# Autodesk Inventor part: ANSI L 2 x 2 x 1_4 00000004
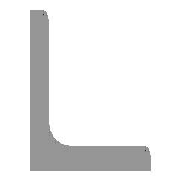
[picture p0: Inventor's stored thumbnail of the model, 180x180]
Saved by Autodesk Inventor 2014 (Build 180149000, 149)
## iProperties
IsCustomPart: 1
Created: 2007-02
Part Number: ANSI L 2 x 2 x 1_4 00000004
Material: Steel, Mild
Document SubType Name: Modeling
Standard: AISC
Designer: Autodesk, Inc.
Size Designation: L 2 x 2 x 1/4
Stock Number: L 2 x 2 x 1/4
Density: 7.86 g/cm^3
Description: Angle Steel
Standards Organization: ANSI
Language: en-US
Categories: <MemberInstance><Categories><Category DisplayName="Structural Shapes" InternalName="089c4875-fa83-4c05-b084-43b9cc11f5ed" Mnemonic="GRDR"><CategoryParameter Dis
Mass: 3582.18 g
Surface Area: 1508.05 cm^2
Volume: 455.748 cm^3
Appearance: Steel
_FrameMemberDoc: Frame Member File
_Version: 15.0.0
_CCFamilyMember: 11
_CCFamilyDisplayName: ANSI L (Equal angles) - Angle Steel
G_L: 31.000 in
G_W: 2.000 in
G_H: 2.000 in
+4F5F36E9-8B8F-4344-9F4B-B9E790CCB65B+CUTDETAIL1: Miter 45.00 deg
+83905929-4DA7-493A-BC2A-CF29B1304FE5+CUTDETAIL2: Miter 45.00 deg
Author: Autodesk, Inc.
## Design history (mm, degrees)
node "Start plane"
node "End plane"
sketch "Sketch"
  geometry: L1 (50.8, 0)-(0, 0); L2 (0, 0)-(0, 50.8); L3 (0, 50.8)-(3.302, 50.8); L4 (6.35, 47.752)-(6.35, 12.7); L5 (12.7, 6.35)-(47.752, 6.35); L6 (50.8, 3.302)-(50.8, 0); L7 (0, -11.041)-(0, 31.538); L8 (-11.041, 0)-(31.538, 0); L9 (0, 63.926)-(0, -23.536) reference; L10 (-23.536, 0)-(63.926, 0) reference; A1 r 6.35 centre (12.7, 12.7) between (6.35, 12.7) and (12.7, 6.35); A2 r 3.048 centre (3.302, 47.752) between (6.35, 47.752) and (3.302, 50.8); A3 r 3.048 centre (47.752, 3.302) between (50.8, 3.302) and (47.752, 6.35); 3 further points
  constraints: 16 end point, 6 point on circle, 6 point on line, 6 tangent, 4 parallel, 3 centre point, 2 collinear, 1 equal radius, 1 horizontal, 1 perpendicular
  dimensions: "d0" = 50.8 distance between parallel lines of L6 L2 (= G_H); "d1" = 50.8 distance between parallel lines of L3 L1 (= G_H); "d2" = 6.35 distance between parallel lines of L2 L4 (= G_T); "d3" = 6.35 distance between parallel lines of L1 L5 (= G_T); "d10" = 0 distance between parallel lines of L7 L2 (computed from ex); "d11" = 0 distance between parallel lines of L8 L1 (computed from d10); "d14" = 6.35 radius of A1 (= G_IR); "d15" = 3.048 radius of A2 (= G_ER)
extrude "Body" new body sketch "Sketch" stored distance "d4" = 787.4 (= G_L); taper "d5" = 0 deg
node "Driven Length"
  sketch "Sketch4"
    geometry: L1 (0, 0)-(10, 0) reference
    constraints: 2 end point, 1 horizontal
  workplane "Work Plane5"
  sketch "Sketch5"
    geometry: L1 (-2, -6.35)-(12, -6.35) reference; L2 (-2, 781.05)-(12, 781.05) reference
    dimensions: "d19" = 787.4 distance between parallel lines of L1 L2 (derived)
workplane "Work Plane3"
split "Split1"
workplane "Work Plane4"
split "Split2"
sketch "Sketch3"
  geometry: C1 r 8.731 at (730.25, 25.4) reference; C2 r 8.731 at (527.05, 25.4) reference; C3 r 8.731 at (260.35, 25.4) reference; C4 r 8.731 at (57.15, 25.4) reference
  constraints: 4 centre point, 8 other
extrude "Extrusion2" cut sketch "Sketch3" stored distance "d16" = 25.4; taper "d17" = 0 deg
body "Solid1"
other parameters: "G_H" = 50.8 [user parameter; used in 2 equation terms], "G_T" = 6.35 [user parameter; used in 2 equation terms], "G_ER" = 3.048 [user parameter; used in 1 equation term], "G_IR" = 6.35 [user parameter; used in 1 equation term], "G_L" = 787.4 (= d19) [user parameter; used in 1 equation term], "ex" = 0 [user parameter; used in 1 equation term], "G_OFFSET_START" = 6.35 [user parameter; used in 1 equation term], "G_OFFSET_END" = 6.35 [user parameter; used in 1 equation term], "d12" = -6.35 (= -G_OFFSET_START), "d13" = 781.05 (= G_OFFSET_END + B_L), "B_L" = 774.7 [user parameter; used in 1 equation term], "d18" = 90 deg
